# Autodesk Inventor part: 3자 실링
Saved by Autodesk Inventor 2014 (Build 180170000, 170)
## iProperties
Created: 2026-09
Part Number: 3자 실링
Material: 고무
Document SubType Name: Modeling
Designer: dg
Density: 0.93 g/cm^3
Appearance: 고무 - 검은색 - 버전 1.1
Mass: 0.673954 g
Surface Area: 12.9646 cm^2
Volume: 0.724682 cm^3
Author: jhkim
Creation Date: 2026-08-26
Sending System: Autodesk Inventor 2027
Preprocessor: ST-DEVELOPER v20.1
Author: dg
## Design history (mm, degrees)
node "3자 실링1"
node "솔리드1"
node "기준1"
